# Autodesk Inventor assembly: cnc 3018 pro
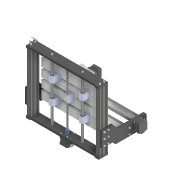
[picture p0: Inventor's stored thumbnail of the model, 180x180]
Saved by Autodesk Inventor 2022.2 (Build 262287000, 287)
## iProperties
Created: 2023-04
Part Number: cnc 3018 pro
Description: STEP AP214
Document SubType Name: Assembly
Designer: 18907419
Sending System: SolidWorks 2023
Preprocessor: SwSTEP 2.0
Title: Baugruppe - Original.STEP
Revision Number: ANY
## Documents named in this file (37)
- C:\Users\18907419\Desktop\cnc_3018-pro_2022\cnc 3018 pro.iam
- C:\Users\18907419\Desktop\cnc_3018-pro_2022\Original - Nutenstein klein M5.ipt
- C:\Users\18907419\Desktop\cnc_3018-pro_2022\Original - Nutenstein M5.ipt
- C:\Users\18907419\Desktop\cnc_3018-pro_2022\Original - Zylinderkopfschraube M4x30.ipt
- C:\Users\18907419\Desktop\cnc_3018-pro_2022\Original - Madenschraube M4x4.ipt
- C:\Users\18907419\Desktop\cnc_3018-pro_2022\Original - Zylinderkopfschraube M3x14.ipt
- C:\Users\18907419\Desktop\cnc_3018-pro_2022\Original - Zylinderkopfschraube M3x20.ipt
- C:\Users\18907419\Desktop\cnc_3018-pro_2022\Original - Zylinderkopfschraube M5x16.ipt
- C:\Users\18907419\Desktop\cnc_3018-pro_2022\Original - Aluminium Profil X.ipt
- C:\Users\18907419\Desktop\cnc_3018-pro_2022\Original - Rahmen X Richtung Y+.ipt
- C:\Users\18907419\Desktop\cnc_3018-pro_2022\Original - Rahmen X Richtung Y-.ipt
- C:\Users\18907419\Desktop\cnc_3018-pro_2022\Original - Aluminium Profil Y.ipt
- C:\Users\18907419\Desktop\cnc_3018-pro_2022\Original - Seitenteil Links.ipt
- C:\Users\18907419\Desktop\cnc_3018-pro_2022\Original - Seitenteil Rechts.ipt
- C:\Users\18907419\Desktop\cnc_3018-pro_2022\Original - Schrittmotor.ipt
- C:\Users\18907419\Desktop\cnc_3018-pro_2022\JST-Steckverbinder-6Pin.ipt
- C:\Users\18907419\Desktop\cnc_3018-pro_2022\Original - Trapezwelle X Achse.ipt
- C:\Users\18907419\Desktop\cnc_3018-pro_2022\Original - Führungswelle Verbinder.ipt
- C:\Users\18907419\Desktop\cnc_3018-pro_2022\Original - KugellagerD16D8H5.ipt
- C:\Users\18907419\Desktop\cnc_3018-pro_2022\Original - T Achse Schrittmotor Träger.ipt
- C:\Users\18907419\Desktop\cnc_3018-pro_2022\Original - Trapezgewindemutter .ipt
- C:\Users\18907419\Desktop\cnc_3018-pro_2022\Original - Trapezgewindemutter Mitnehmer .ipt
- C:\Users\18907419\Desktop\cnc_3018-pro_2022\Original - Trapezgewindemutter Gehäuse.ipt
- C:\Users\18907419\Desktop\cnc_3018-pro_2022\Original - Trapezwelle Y Achse.ipt
- C:\Users\18907419\Desktop\cnc_3018-pro_2022\Original - Spacer Schrittmotor.ipt
- C:\Users\18907419\Desktop\cnc_3018-pro_2022\Original - Trapezwelle Z Achse.ipt
- C:\Users\18907419\Desktop\cnc_3018-pro_2022\Original - Spindelhalter.ipt
- C:\Users\18907419\Desktop\cnc_3018-pro_2022\Original - Kontermutter Spindelhalter.ipt
- C:\Users\18907419\Desktop\cnc_3018-pro_2022\Original - Führungswelle X.ipt
- C:\Users\18907419\Desktop\cnc_3018-pro_2022\Original - LinearlagerA19I10.ipt
- C:\Users\18907419\Desktop\cnc_3018-pro_2022\Original - Linearlager Gehäuse.ipt
- C:\Users\18907419\Desktop\cnc_3018-pro_2022\Original - Führungswelle Y.ipt
- C:\Users\18907419\Desktop\cnc_3018-pro_2022\Original - Führungswelle Z.ipt
- C:\Users\18907419\Desktop\cnc_3018-pro_2022\Original - LinearlagerA15I8.ipt
- C:\Users\18907419\Desktop\cnc_3018-pro_2022\Original - Spindelmotor.ipt
- C:\Users\18907419\Desktop\cnc_3018-pro_2022\Original - Spindelmotor Überwurfmutter.ipt
- C:\Users\18907419\Desktop\cnc_3018-pro_2022\Original - Tisch.ipt
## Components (131 placed, 131 different names)
1. Original - Nutenstein klein M5_1
2. Original - Nutenstein klein M5_2
3. Original - Nutenstein klein M5_3
4. Original - Nutenstein klein M5_4
5. Original - Nutenstein klein M5_5
6. Original - Nutenstein klein M5_6
7. Original - Nutenstein klein M5_7
8. Original - Nutenstein klein M5_8
9. Original - Nutenstein klein M5_9
10. Original - Nutenstein klein M5_10
11. Original - Nutenstein klein M5_11
12. Original - Nutenstein klein M5_12
13. Original - Nutenstein M5_21 — Rotazionale:35, Angolo:7, Angolo:8
14. Original - Nutenstein M5_22 — Rotazionale:34, Angolo:8
15. Original - Zylinderkopfschraube M4x30_23 — Rotazionale:5
16. Original - Madenschraube M4x4_24 — Rigido:4
17. Original - Madenschraube M4x4_27 — Rigido:3
18. Original - Madenschraube M4x4_28
19. Original - Madenschraube M4x4_29
20. Original - Madenschraube M4x4_30
21. Original - Madenschraube M4x4_31
22. Original - Madenschraube M4x4_32 — Rigido:9
23. Original - Madenschraube M4x4_33 — Rigido:8
24. Original - Madenschraube M4x4_34 — Rigido:6
25. Original - Madenschraube M4x4_35 — Rigido:7
26. Original - Zylinderkopfschraube M3x14_36
27. Original - Zylinderkopfschraube M3x14_37
28. Original - Zylinderkopfschraube M3x14_38
29. Original - Zylinderkopfschraube M3x14_39
30. Original - Zylinderkopfschraube M3x14_40
31. Original - Zylinderkopfschraube M3x14_41
32. Original - Zylinderkopfschraube M3x14_42
33. Original - Zylinderkopfschraube M3x14_43
34. Original - Zylinderkopfschraube M3x20_44 — Rotazionale:17
35. Original - Zylinderkopfschraube M3x20_45 — Rotazionale:16
36. Original - Zylinderkopfschraube M3x20_46 — Rotazionale:18
37. Original - Zylinderkopfschraube M3x20_47 — Rotazionale:19
38. Original - Zylinderkopfschraube M5x16_48
39. Original - Zylinderkopfschraube M5x16_49
40. Original - Zylinderkopfschraube M5x16_50
41. Original - Zylinderkopfschraube M5x16_51
42. Original - Zylinderkopfschraube M5x16_52
43. Original - Zylinderkopfschraube M5x16_53
44. Original - Zylinderkopfschraube M5x16_54
45. Original - Zylinderkopfschraube M5x16_55
46. Original - Zylinderkopfschraube M5x16_56
47. Original - Zylinderkopfschraube M5x16_57
48. Original - Zylinderkopfschraube M5x16_58
49. Original - Zylinderkopfschraube M5x16_59
50. Original - Zylinderkopfschraube M5x16_60
51. Original - Zylinderkopfschraube M5x16_61
52. Original - Zylinderkopfschraube M5x16_62
53. Original - Zylinderkopfschraube M5x16_63
54. Original - Zylinderkopfschraube M5x16_64
55. Original - Zylinderkopfschraube M5x16_65
56. Original - Zylinderkopfschraube M5x16_66
57. Original - Zylinderkopfschraube M5x16_67
58. Original - Zylinderkopfschraube M5x16_68
59. Original - Zylinderkopfschraube M5x16_69
60. Original - Zylinderkopfschraube M5x16_70
61. Original - Zylinderkopfschraube M5x16_71
62. Original - Zylinderkopfschraube M5x16_72
63. Original - Zylinderkopfschraube M5x16_73
64. Original - Zylinderkopfschraube M5x16_74
65. Original - Zylinderkopfschraube M5x16_75
66. Original - Zylinderkopfschraube M5x16_76
67. Original - Zylinderkopfschraube M5x16_77
68. Original - Zylinderkopfschraube M5x16_78
69. Original - Zylinderkopfschraube M5x16_79
70. Original - Zylinderkopfschraube M5x16_80
71. Original - Zylinderkopfschraube M5x16_89 — Rotazionale:33
72. Original - Zylinderkopfschraube M5x16_90 — Rotazionale:32
73. Original - Aluminium Profil X_91
74. Original - Aluminium Profil X_92
75. Original - Rahmen X Richtung Y+_93
76. Original - Rahmen X Richtung Y-_94 — Angolo:5, Coincidente:13, Allineato:6, Coincidente:18
77. Original - Aluminium Profil Y_95
78. Original - Aluminium Profil Y_96 — Coincidente:16
79. Original - Seitenteil Links_97 — Coincidente:19
80. Original - Seitenteil Rechts_98
81. Original - Schrittmotor_99
82. Original - Trapezwelle X Achse_101
83. Original - Führungswelle Verbinder_102
84. Original - KugellagerD16D8H5_103
85. Original - T Achse Schrittmotor Träger_104 — Rotazionale:8, Rotazionale:9, Rotazionale:10, Rotazionale:11, Rotazionale:12, Rotazionale:13, Coincidente:2, Angolo:4, Rotazionale:16, Rotazionale:17, Rotazionale:18, Rotazionale:19, Coincidente:3, Rotazionale:21, Rotazionale:22, Rotazionale:23, Rotazionale:24, Rotazionale:25, Coincidente:4, Coincidente:5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
86. Original - Trapezgewindemutter _105 — Rotazionale:26
87. Original - Trapezgewindemutter Mitnehmer _106 — Rotazionale:25
88. Original - Schrittmotor_107 — Rotazionale:36
89. JST-Steckverbinder-6Pin_108
90. Original - Trapezgewindemutter _109 — Rotazionale:30
91. Original - Trapezgewindemutter Mitnehmer _110 — Rotazionale:31, Angolo:6
92. Original - Trapezgewindemutter Gehäuse_111 — Coincidente:10, Allineato:3, Allineato:4, Angolo:5, Rotazionale:30, Rotazionale:31, Angolo:6, Rotazionale:32, Rotazionale:33, Rotazionale:34, Rotazionale:35, Angolo:7, Coincidente:17
93. Original - Trapezwelle Y Achse_112 — Coincidente:10, Coincidente:13, Allineato:6
94. Original - Führungswelle Verbinder_113 — Rotazionale:36, Rigido:6, Rigido:7, Rigido:8, Rigido:9
95. Original - KugellagerD16D8H5_114
96. Original - Schrittmotor_115 — Coincidente:2, Rotazionale:14, Angolo:4, Rotazionale:15
97. Original - Spacer Schrittmotor_116 — Rotazionale:12
98. Original - Spacer Schrittmotor_117 — Rotazionale:10
99. Original - Spacer Schrittmotor_118 — Rotazionale:11, Rotazionale:14
100. Original - Spacer Schrittmotor_119 — Rotazionale:13
101. Original - Trapezwelle Z Achse_121 — Coincidente:3, Rotazionale:20
102. Original - Führungswelle Verbinder_122 — Rotazionale:15, Rigido:3, Rigido:4, Rotazionale:20
103. Original - Spindelhalter_123 — Coincidente:1, Allineato:1, Angolo:1, Rotazionale:1, Rotazionale:2, Rotazionale:3, Rotazionale:4, Rotazionale:5, Rotazionale:6, Angolo:2, Rotazionale:7, Angolo:3, Rigido:2, Coincidente:20
104. Original - Kontermutter Spindelhalter_124 — Rotazionale:6, Angolo:2
105. Original - Trapezgewindemutter _125 — Rigido:2
106. Original - Trapezgewindemutter Mitnehmer _126 — Rotazionale:7, Angolo:3
107. Original - Führungswelle X_127 — Coincidente:4
108. Original - Führungswelle X_128 — Coincidente:5
109. Original - LinearlagerA19I10_129 — Rotazionale:22
110. Original - LinearlagerA19I10_130 — Rotazionale:21
111. Original - LinearlagerA19I10_131 — Rotazionale:23
112. Original - LinearlagerA19I10_132 — Rotazionale:24
113. Original - Linearlager Gehäuse_133 — Coincidente:11, Rigido:5, Allineato:5, Allineato:8
114. Original - LinearlagerA19I10_134 — Rigido:5
115. Original - Linearlager Gehäuse_135 — Coincidente:11, Coincidente:12, Rotazionale:29, Allineato:4, Allineato:5, Allineato:7
116. Original - LinearlagerA19I10_136 — Rotazionale:29
117. Original - Linearlager Gehäuse_137 — Coincidente:9, Rotazionale:28, Allineato:2, Allineato:3, Allineato:8, Coincidente:14, Coincidente:15, Allineato:9, Coincidente:17
118. Original - LinearlagerA19I10_138 — Rotazionale:28
119. Original - Linearlager Gehäuse_139 — Rotazionale:27, Coincidente:8, Allineato:2, Allineato:7, Coincidente:14
120. Original - LinearlagerA19I10_140 — Rotazionale:27
121. Original - Führungswelle Y_141 — Coincidente:8, Coincidente:9
122. Original - Führungswelle Y_142 — Coincidente:12
123. Original - Führungswelle Z_143 — Rotazionale:8, Coincidente:7
124. Original - Führungswelle Z_144 — Rotazionale:9, Coincidente:6
125. Original - LinearlagerA15I8_145 — Rotazionale:2
126. Original - LinearlagerA15I8_146 — Rotazionale:4
127. Original - LinearlagerA15I8_147 — Rotazionale:1, Coincidente:6
128. Original - LinearlagerA15I8_148 — Rotazionale:3, Coincidente:7
129. Original - Spindelmotor_149 — Rigido:1, Coincidente:1, Allineato:1, Angolo:1
130. Original - Spindelmotor Überwurfmutter_152 — Rigido:1
131. Original - Tisch_153 — Coincidente:15, Coincidente:16, Allineato:9, Coincidente:18
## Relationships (82: RevoluteJoint 36, Mate 20, WeldJoint 9, Flush 9, Angle 8)
- Rigido:1 [WeldJoint]: Original - Spindelmotor_149 ↔ Original - Spindelmotor Überwurfmutter_152
- Coincidente:1 [Mate]: Original - Spindelhalter_123 ↔ Original - Spindelmotor_149
- Allineato:1 [Flush]: Original - Spindelhalter_123 ↔ Original - Spindelmotor_149
- Angolo:1 [Angle]: Original - Spindelhalter_123 ↔ Original - Spindelmotor_149
- Rotazionale:1 [RevoluteJoint]: Original - Spindelhalter_123 ↔ Original - LinearlagerA15I8_147
- Rotazionale:2 [RevoluteJoint]: Original - Spindelhalter_123 ↔ Original - LinearlagerA15I8_145
- Rotazionale:3 [RevoluteJoint]: Original - Spindelhalter_123 ↔ Original - LinearlagerA15I8_148
- Rotazionale:4 [RevoluteJoint]: Original - Spindelhalter_123 ↔ Original - LinearlagerA15I8_146
- Rotazionale:5 [RevoluteJoint]: Original - Zylinderkopfschraube M4x30_23 ↔ Original - Spindelhalter_123
- Rotazionale:6 [RevoluteJoint]: Original - Spindelhalter_123 ↔ Original - Kontermutter Spindelhalter_124
- Angolo:2 [Angle]: Original - Spindelhalter_123 ↔ Original - Kontermutter Spindelhalter_124
- Rotazionale:7 [RevoluteJoint]: Original - Spindelhalter_123 ↔ Original - Trapezgewindemutter Mitnehmer _126
- Angolo:3 [Angle]: Original - Spindelhalter_123 ↔ Original - Trapezgewindemutter Mitnehmer _126
- Rigido:2 [WeldJoint]: Original - Spindelhalter_123 ↔ Original - Trapezgewindemutter _125
- Rotazionale:8 [RevoluteJoint]: Original - T Achse Schrittmotor Träger_104 ↔ Original - Führungswelle Z_143
- Rotazionale:9 [RevoluteJoint]: Original - T Achse Schrittmotor Träger_104 ↔ Original - Führungswelle Z_144
- Rotazionale:10 [RevoluteJoint]: Original - T Achse Schrittmotor Träger_104 ↔ Original - Spacer Schrittmotor_117
- Rotazionale:11 [RevoluteJoint]: Original - T Achse Schrittmotor Träger_104 ↔ Original - Spacer Schrittmotor_118
- Rotazionale:12 [RevoluteJoint]: Original - T Achse Schrittmotor Träger_104 ↔ Original - Spacer Schrittmotor_116
- Rotazionale:13 [RevoluteJoint]: Original - T Achse Schrittmotor Träger_104 ↔ Original - Spacer Schrittmotor_119
- Coincidente:2 [Mate]: Original - T Achse Schrittmotor Träger_104 ↔ Original - Schrittmotor_115
- Rotazionale:14 [RevoluteJoint]: Original - Schrittmotor_115 ↔ Original - Spacer Schrittmotor_118
- Angolo:4 [Angle]: Original - T Achse Schrittmotor Träger_104 ↔ Original - Schrittmotor_115
- Rotazionale:15 [RevoluteJoint]: Original - Schrittmotor_115 ↔ Original - Führungswelle Verbinder_122
- Rigido:3 [WeldJoint]: Original - Madenschraube M4x4_27 ↔ Original - Führungswelle Verbinder_122
- Rigido:4 [WeldJoint]: Original - Madenschraube M4x4_24 ↔ Original - Führungswelle Verbinder_122
- Rotazionale:16 [RevoluteJoint]: Original - Zylinderkopfschraube M3x20_45 ↔ Original - T Achse Schrittmotor Träger_104
- Rotazionale:17 [RevoluteJoint]: Original - Zylinderkopfschraube M3x20_44 ↔ Original - T Achse Schrittmotor Träger_104
- Rotazionale:18 [RevoluteJoint]: Original - Zylinderkopfschraube M3x20_46 ↔ Original - T Achse Schrittmotor Träger_104
- Rotazionale:19 [RevoluteJoint]: Original - Zylinderkopfschraube M3x20_47 ↔ Original - T Achse Schrittmotor Träger_104
- Coincidente:3 [Mate]: Original - T Achse Schrittmotor Träger_104 ↔ Original - Trapezwelle Z Achse_121
- Rotazionale:20 [RevoluteJoint]: Original - Trapezwelle Z Achse_121 ↔ Original - Führungswelle Verbinder_122
- Rotazionale:21 [RevoluteJoint]: Original - T Achse Schrittmotor Träger_104 ↔ Original - LinearlagerA19I10_130
- Rotazionale:22 [RevoluteJoint]: Original - T Achse Schrittmotor Träger_104 ↔ Original - LinearlagerA19I10_129
- Rotazionale:23 [RevoluteJoint]: Original - T Achse Schrittmotor Träger_104 ↔ Original - LinearlagerA19I10_131
- Rotazionale:24 [RevoluteJoint]: Original - T Achse Schrittmotor Träger_104 ↔ Original - LinearlagerA19I10_132
- Rotazionale:25 [RevoluteJoint]: Original - T Achse Schrittmotor Träger_104 ↔ Original - Trapezgewindemutter Mitnehmer _106
- Coincidente:4 [Mate]: Original - T Achse Schrittmotor Träger_104 ↔ Original - Führungswelle X_127
- Coincidente:5 [Mate]: Original - T Achse Schrittmotor Träger_104 ↔ Original - Führungswelle X_128
- Rotazionale:26 [RevoluteJoint]: Original - T Achse Schrittmotor Träger_104 ↔ Original - Trapezgewindemutter _105
- Coincidente:6 [Mate]: Original - Führungswelle Z_144 ↔ Original - LinearlagerA15I8_147
- Coincidente:7 [Mate]: Original - Führungswelle Z_143 ↔ Original - LinearlagerA15I8_148
- Rotazionale:27 [RevoluteJoint]: Original - Linearlager Gehäuse_139 ↔ Original - LinearlagerA19I10_140
- Coincidente:8 [Mate]: Original - Linearlager Gehäuse_139 ↔ Original - Führungswelle Y_141
- Coincidente:9 [Mate]: Original - Linearlager Gehäuse_137 ↔ Original - Führungswelle Y_141
- Coincidente:10 [Mate]: Original - Trapezgewindemutter Gehäuse_111 ↔ Original - Trapezwelle Y Achse_112
- Coincidente:11 [Mate]: Original - Linearlager Gehäuse_133 ↔ Original - Linearlager Gehäuse_135
- Coincidente:12 [Mate]: Original - Linearlager Gehäuse_135 ↔ Original - Führungswelle Y_142
- Rotazionale:28 [RevoluteJoint]: Original - Linearlager Gehäuse_137 ↔ Original - LinearlagerA19I10_138
- Rigido:5 [WeldJoint]: Original - Linearlager Gehäuse_133 ↔ Original - LinearlagerA19I10_134
- Rotazionale:29 [RevoluteJoint]: Original - Linearlager Gehäuse_135 ↔ Original - LinearlagerA19I10_136
- Allineato:2 [Flush]: Original - Linearlager Gehäuse_137 ↔ Original - Linearlager Gehäuse_139
- Allineato:3 [Flush]: Original - Trapezgewindemutter Gehäuse_111 ↔ Original - Linearlager Gehäuse_137
- Allineato:4 [Flush]: Original - Trapezgewindemutter Gehäuse_111 ↔ Original - Linearlager Gehäuse_135
- Allineato:5 [Flush]: Original - Linearlager Gehäuse_133 ↔ Original - Linearlager Gehäuse_135
- Angolo:5 [Angle]: Original - Rahmen X Richtung Y-_94 ↔ Original - Trapezgewindemutter Gehäuse_111
- Coincidente:13 [Mate]: Original - Rahmen X Richtung Y-_94 ↔ Original - Trapezwelle Y Achse_112
- Allineato:6 [Flush]: Original - Rahmen X Richtung Y-_94 ↔ Original - Trapezwelle Y Achse_112
- Rotazionale:30 [RevoluteJoint]: Original - Trapezgewindemutter _109 ↔ Original - Trapezgewindemutter Gehäuse_111
- Rotazionale:31 [RevoluteJoint]: Original - Trapezgewindemutter Mitnehmer _110 ↔ Original - Trapezgewindemutter Gehäuse_111
- Angolo:6 [Angle]: Original - Trapezgewindemutter Mitnehmer _110 ↔ Original - Trapezgewindemutter Gehäuse_111
- Rotazionale:32 [RevoluteJoint]: Original - Zylinderkopfschraube M5x16_90 ↔ Original - Trapezgewindemutter Gehäuse_111
- Rotazionale:33 [RevoluteJoint]: Original - Zylinderkopfschraube M5x16_89 ↔ Original - Trapezgewindemutter Gehäuse_111
- Rotazionale:34 [RevoluteJoint]: Original - Nutenstein M5_22 ↔ Original - Trapezgewindemutter Gehäuse_111
- Rotazionale:35 [RevoluteJoint]: Original - Nutenstein M5_21 ↔ Original - Trapezgewindemutter Gehäuse_111
- Angolo:7 [Angle]: Original - Nutenstein M5_21 ↔ Original - Trapezgewindemutter Gehäuse_111
- Angolo:8 [Angle]: Original - Nutenstein M5_21 ↔ Original - Nutenstein M5_22
- Rotazionale:36 [RevoluteJoint]: Original - Schrittmotor_107 ↔ Original - Führungswelle Verbinder_113
- Rigido:6 [WeldJoint]: Original - Madenschraube M4x4_34 ↔ Original - Führungswelle Verbinder_113
- Rigido:7 [WeldJoint]: Original - Madenschraube M4x4_35 ↔ Original - Führungswelle Verbinder_113
- Rigido:8 [WeldJoint]: Original - Madenschraube M4x4_33 ↔ Original - Führungswelle Verbinder_113
- Rigido:9 [WeldJoint]: Original - Madenschraube M4x4_32 ↔ Original - Führungswelle Verbinder_113
- Allineato:7 [Flush]: Original - Linearlager Gehäuse_135 ↔ Original - Linearlager Gehäuse_139
- Allineato:8 [Flush]: Original - Linearlager Gehäuse_133 ↔ Original - Linearlager Gehäuse_137
- Coincidente:14 [Mate]: Original - Linearlager Gehäuse_137 ↔ Original - Linearlager Gehäuse_139
- Coincidente:15 [Mate]: Original - Linearlager Gehäuse_137 ↔ Original - Tisch_153
- Coincidente:16 [Mate]: Original - Aluminium Profil Y_96 ↔ Original - Tisch_153
- Allineato:9 [Flush]: Original - Linearlager Gehäuse_137 ↔ Original - Tisch_153
- Coincidente:17 [Mate]: Original - Trapezgewindemutter Gehäuse_111 ↔ Original - Linearlager Gehäuse_137
- Coincidente:18 [Mate]: Original - Rahmen X Richtung Y-_94 ↔ Original - Tisch_153
- Coincidente:19 [Mate]: Original - Seitenteil Links_97 ↔ Original - T Achse Schrittmotor Träger_104
- Coincidente:20 [Mate]: Original - T Achse Schrittmotor Träger_104 ↔ Original - Spindelhalter_123
